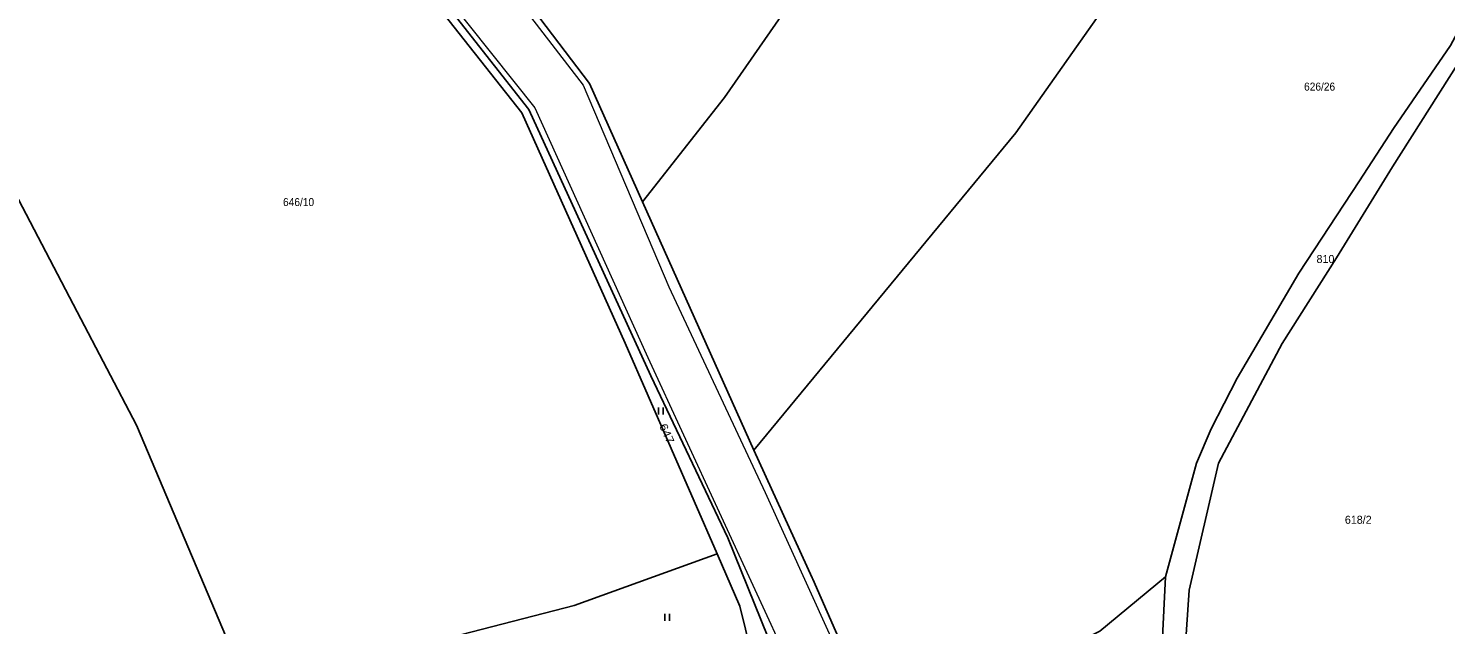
# Model space of a CAD drawing. Extents: x -687135 to -684370, y -1007309 to -1005782.
# Drawn here: x -685221.9 to -684920.8, y -1006444.6 to -1006317.9 of the extents above; entities that cross this region are included whole.
import ezdxf

# ---------------------------------------------------------------- set-up
doc = ezdxf.new("R2010")
doc.units = 0
doc.header["$LTSCALE"] = 0.68
for name, color, linetype, lineweight in [('1', 7, 'Continuous', 25), ('3', 7, 'Continuous', 25), ('4', 7, 'Continuous', 13)]:
    doc.layers.add(name, color=color, linetype=linetype, lineweight=lineweight)
doc.layers.add('2', color=7, linetype='Continuous')

msp = doc.modelspace()

# ---------------------------------------------------------------- linework, layer by layer
at = {"layer": '1'}
for points in [[(-684930.17, -1006108.46), (-684936.09, -1006119.13), (-684954.55, -1006149.28), (-684993.37, -1006215.25), (-685051.21, -1006299.76), (-685074, -1006332.62), (-685091.4, -1006354.8)], [(-685067.76, -1006407.52), (-685012.1, -1006340.15), (-684940.88, -1006239.13), (-684910.26, -1006197.91), (-684889.9, -1006169.75), (-684877.93, -1006152.74), (-684876.78, -1006150.79)], [(-684856.23, -1006219.78), (-684868.36, -1006236.18), (-684877.16, -1006249.29), (-684887.91, -1006266.51), (-684898.63, -1006286.6), (-684913.88, -1006310.63), (-684919.75, -1006321.58), (-684931.87, -1006339.19), (-684939.11, -1006350.34), (-684952.01, -1006369.9), (-684965.12, -1006392.2), (-684970.59, -1006402.96), (-684973.76, -1006410.29), (-684980.32, -1006434.42)], [(-685061.94, -1006454.16), (-685073.28, -1006426.13), (-685089.64, -1006391.69), (-685115.59, -1006335.15), (-685153.62, -1006286.74), (-685198.1, -1006232.27)], [(-685199.53, -1006233.83), (-685155.92, -1006286.6), (-685117.05, -1006335.89), (-685095.12, -1006384.78), (-685075.56, -1006429.52)], [(-685175.13, -1006458.36), (-685198.89, -1006402.17), (-685211.49, -1006378.14), (-685237.4, -1006328.81), (-685256.82, -1006291)], [(-684900.57, -1006302.99), (-684907.23, -1006311.42), (-684918.18, -1006325.47), (-684932.07, -1006347.35), (-684944, -1006366.68), (-684955.53, -1006384.87), (-684969.03, -1006410.25), (-684975.28, -1006437.24), (-684977.83, -1006474.8), (-684979.92, -1006493.97)], [(-685091.4, -1006354.8), (-685102.68, -1006329.65), (-685117.08, -1006310.67)], [(-685040.8, -1006467.83), (-685055.26, -1006434.88), (-685055.37, -1006434.63), (-685067.76, -1006407.52), (-685091.4, -1006354.8)], [(-685075.56, -1006429.52), (-685105.97, -1006440.47), (-685149.59, -1006451.75), (-685175.13, -1006458.36)], [(-685067.19, -1006455.02), (-685070.72, -1006440.65), (-685075.56, -1006429.52)], [(-685020.6, -1006508.76), (-685000.01, -1006502.31), (-684988.15, -1006495.16), (-684982.57, -1006480.15), (-684980.32, -1006434.42)], [(-684980.32, -1006434.42), (-684994.25, -1006445.97), (-685018.29, -1006458.13)]]:
    msp.add_lwpolyline(points, dxfattribs=at)
at = {"layer": '3'}
for p, q in [((-685088.031, -1006399.94), (-685088.031, -1006398.44)), ((-685087.03, -1006399.94), (-685087.03, -1006398.44)), ((-685086.661, -1006443.77), (-685086.661, -1006442.27)), ((-685085.66, -1006443.77), (-685085.66, -1006442.27))]:
    msp.add_line(p, q, dxfattribs=at)
at = {"layer": '4'}
for p, q in [((-685170.68, -1006263.96), (-685114.29, -1006334.81)), ((-685114.29, -1006334.81), (-685090.32, -1006387.84)), ((-685085.82, -1006372.79), (-685065.37, -1006416.52))]:
    msp.add_line(p, q, dxfattribs=at)
for points in [[(-685215.86, -1006195.64), (-685208.32, -1006202.04), (-685182.9, -1006229.69), (-685142.36, -1006280.22), (-685104.01, -1006330), (-685085.82, -1006372.79)], [(-685090.32, -1006387.84), (-685060, -1006453.51), (-685036.24, -1006506.98), (-685026.12, -1006521.97)], [(-685065.37, -1006416.52), (-685042.68, -1006466.37), (-685032.4, -1006488.74), (-685022.44, -1006509.59), (-684967.45, -1006559.07), (-684916.25, -1006603.35), (-684856.74, -1006654.98), (-684782.53, -1006719.91)]]:
    msp.add_lwpolyline(points, dxfattribs=at)

# ---------------------------------------------------------------- texts
at = {"layer": '2', "width": 0.95}
for s, p in [('626/26', (-684950.88, -1006331.15)), ('646/10', (-685167.79, -1006355.669))]:
    msp.add_text(s, height=1.7, dxfattribs=at).set_placement(p)
at = {"layer": '2'}
for s, p in [('810', (-684948.23, -1006367.76)), ('618/2', (-684942.21, -1006423.13))]:
    msp.add_text(s, height=1.7, dxfattribs=at).set_placement(p)
at = {"layer": '2', "width": 1.15}
msp.add_text('647', height=1.7, rotation=294, dxfattribs=at).set_placement((-685087.916, -1006402.325))

doc.saveas('drawing.dxf')
